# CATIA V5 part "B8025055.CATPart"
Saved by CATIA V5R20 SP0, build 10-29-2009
Part number: B8025055
Revision: 11
Definition: design
Nomenclature: B8025055
Source: made
Description: NOT SPECIFIED
Bounding box of the stored display mesh (mm): x -38 to 38, y -38 to 38, z -25 to 55
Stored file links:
  C:\Users\Utente\Desktop\3D files B802\B8025055.CATPart
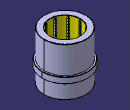
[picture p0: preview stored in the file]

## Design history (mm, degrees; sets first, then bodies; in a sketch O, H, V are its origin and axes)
Body1 "MANIFOLD_SOLID_BREP #38" (main body)
  Solid1: solid without history
Body2 "MANIFOLD_SOLID_BREP #76"
  Solid2: solid without history
Body3 "MANIFOLD_SOLID_BREP #114"
  Solid3: solid without history
Body4 "MANIFOLD_SOLID_BREP #152"
  Solid4: solid without history
Body5 "MANIFOLD_SOLID_BREP #190"
  Solid5: solid without history
Body6 "MANIFOLD_SOLID_BREP #228"
  Solid6: solid without history
Body7 "MANIFOLD_SOLID_BREP #266"
  Solid7: solid without history
Body8 "MANIFOLD_SOLID_BREP #304"
  Solid8: solid without history
Body9 "MANIFOLD_SOLID_BREP #2774"
  Solid9: solid without history
Body10 "MANIFOLD_SOLID_BREP #2812"
  Solid10: solid without history
Body11 "MANIFOLD_SOLID_BREP #2850"
  Solid11: solid without history
Body12 "MANIFOLD_SOLID_BREP #2888"
  Solid12: solid without history
Body13 "MANIFOLD_SOLID_BREP #2926"
  Solid13: solid without history
Body14 "MANIFOLD_SOLID_BREP #2964"
  Solid14: solid without history
Body15 "MANIFOLD_SOLID_BREP #3002"
  Solid15: solid without history
Body16 "MANIFOLD_SOLID_BREP #3040"
  Solid16: solid without history
Body17 "MANIFOLD_SOLID_BREP #3078"
  Solid17: solid without history
Body18 "MANIFOLD_SOLID_BREP #3116"
  Solid18: solid without history
Body19 "MANIFOLD_SOLID_BREP #3154"
  Solid19: solid without history
Body20 "MANIFOLD_SOLID_BREP #3192"
  Solid20: solid without history
Body21 "MANIFOLD_SOLID_BREP #3230"
  Solid21: solid without history
Body22 "MANIFOLD_SOLID_BREP #3268"
  Solid22: solid without history
Body23 "MANIFOLD_SOLID_BREP #3306"
  Solid23: solid without history
Body24 "MANIFOLD_SOLID_BREP #3344"
  Solid24: solid without history
Body25 "MANIFOLD_SOLID_BREP #3382"
  Solid25: solid without history
Body26 "MANIFOLD_SOLID_BREP #3420"
  Solid26: solid without history
Body27 "MANIFOLD_SOLID_BREP #3458"
  Solid27: solid without history
Body28 "MANIFOLD_SOLID_BREP #3496"
  Solid28: solid without history
Body29 "MANIFOLD_SOLID_BREP #3534"
  Solid29: solid without history
Body30 "MANIFOLD_SOLID_BREP #3572"
  Solid30: solid without history
Body31 "MANIFOLD_SOLID_BREP #3610"
  Solid31: solid without history
Body32 "MANIFOLD_SOLID_BREP #3648"
  Solid32: solid without history
Body33 "MANIFOLD_SOLID_BREP #3686"
  Solid33: solid without history
Body34 "MANIFOLD_SOLID_BREP #3724"
  Solid34: solid without history
Body35 "MANIFOLD_SOLID_BREP #3762"
  Solid35: solid without history
Body36 "MANIFOLD_SOLID_BREP #3800"
  Solid36: solid without history
Body37 "MANIFOLD_SOLID_BREP #3838"
  Solid37: solid without history
Body38 "MANIFOLD_SOLID_BREP #3876"
  Solid38: solid without history
Body39 "MANIFOLD_SOLID_BREP #3914"
  Solid39: solid without history
Body40 "MANIFOLD_SOLID_BREP #3952"
  Solid40: solid without history
Body41 "MANIFOLD_SOLID_BREP #3990"
  Solid41: solid without history
Body42 "MANIFOLD_SOLID_BREP #4028"
  Solid42: solid without history
Body43 "MANIFOLD_SOLID_BREP #4066"
  Solid43: solid without history
Body44 "MANIFOLD_SOLID_BREP #4104"
  Solid44: solid without history
Body45 "MANIFOLD_SOLID_BREP #4142"
  Solid45: solid without history
Body46 "MANIFOLD_SOLID_BREP #4180"
  Solid46: solid without history
Body47 "MANIFOLD_SOLID_BREP #4218"
  Solid47: solid without history
Body48 "MANIFOLD_SOLID_BREP #4256"
  Solid48: solid without history
Body49 "MANIFOLD_SOLID_BREP #4294"
  Solid49: solid without history
Body50 "MANIFOLD_SOLID_BREP #4332"
  Solid50: solid without history
Body51 "MANIFOLD_SOLID_BREP #4370"
  Solid51: solid without history
Body52 "MANIFOLD_SOLID_BREP #4408"
  Solid52: solid without history
Body53 "MANIFOLD_SOLID_BREP #4446"
  Solid53: solid without history
Body54 "MANIFOLD_SOLID_BREP #4484"
  Solid54: solid without history
Body55 "MANIFOLD_SOLID_BREP #4522"
  Solid55: solid without history
Body56 "MANIFOLD_SOLID_BREP #4560"
  Solid56: solid without history
Body57 "MANIFOLD_SOLID_BREP #4598"
  Solid57: solid without history
Body58 "MANIFOLD_SOLID_BREP #4636"
  Solid58: solid without history
Body59 "MANIFOLD_SOLID_BREP #4674"
  Solid59: solid without history
Body60 "MANIFOLD_SOLID_BREP #4712"
  Solid60: solid without history
Body61 "MANIFOLD_SOLID_BREP #4750"
  Solid61: solid without history
Body62 "MANIFOLD_SOLID_BREP #4788"
  Solid62: solid without history
Body63 "MANIFOLD_SOLID_BREP #4826"
  Solid63: solid without history
Body64 "MANIFOLD_SOLID_BREP #4864"
  Solid64: solid without history
Body65 "MANIFOLD_SOLID_BREP #4902"
  Solid65: solid without history
Body66 "MANIFOLD_SOLID_BREP #4940"
  Solid66: solid without history
Body67 "MANIFOLD_SOLID_BREP #4978"
  Solid67: solid without history
Body68 "MANIFOLD_SOLID_BREP #5016"
  Solid68: solid without history
Body69 "MANIFOLD_SOLID_BREP #5054"
  Solid69: solid without history
Body70 "MANIFOLD_SOLID_BREP #5092"
  Solid70: solid without history
Body71 "MANIFOLD_SOLID_BREP #5130"
  Solid71: solid without history
Body72 "MANIFOLD_SOLID_BREP #5168"
  Solid72: solid without history
Body73 "MANIFOLD_SOLID_BREP #5206"
  Solid73: solid without history
Body74 "MANIFOLD_SOLID_BREP #5244"
  Solid74: solid without history
Body75 "MANIFOLD_SOLID_BREP #5282"
  Solid75: solid without history
Body76 "MANIFOLD_SOLID_BREP #5320"
  Solid76: solid without history
Body77 "MANIFOLD_SOLID_BREP #5358"
  Solid77: solid without history
Body78 "MANIFOLD_SOLID_BREP #5396"
  Solid78: solid without history
Body79 "MANIFOLD_SOLID_BREP #5434"
  Solid79: solid without history
Body80 "MANIFOLD_SOLID_BREP #5472"
  Solid80: solid without history
Body81 "MANIFOLD_SOLID_BREP #5510"
  Solid81: solid without history
Body82 "MANIFOLD_SOLID_BREP #5548"
  Solid82: solid without history
Body83 "MANIFOLD_SOLID_BREP #5586"
  Solid83: solid without history
Body84 "MANIFOLD_SOLID_BREP #5624"
  Solid84: solid without history
Body85 "MANIFOLD_SOLID_BREP #5662"
  Solid85: solid without history
Body86 "MANIFOLD_SOLID_BREP #5700"
  Solid86: solid without history
Body87 "MANIFOLD_SOLID_BREP #5738"
  Solid87: solid without history
Body88 "MANIFOLD_SOLID_BREP #5776"
  Solid88: solid without history
Body89 "MANIFOLD_SOLID_BREP #5814"
  Solid89: solid without history
Body90 "MANIFOLD_SOLID_BREP #5852"
  Solid90: solid without history
Body91 "MANIFOLD_SOLID_BREP #5890"
  Solid91: solid without history
Body92 "MANIFOLD_SOLID_BREP #5928"
  Solid92: solid without history
Body93 "MANIFOLD_SOLID_BREP #5966"
  Solid93: solid without history
Body94 "MANIFOLD_SOLID_BREP #6004"
  Solid94: solid without history
Body95 "MANIFOLD_SOLID_BREP #6042"
  Solid95: solid without history
Body96 "MANIFOLD_SOLID_BREP #6080"
  Solid96: solid without history
Body97 "MANIFOLD_SOLID_BREP #6118"
  Solid97: solid without history
Body98 "MANIFOLD_SOLID_BREP #6156"
  Solid98: solid without history
Body99 "MANIFOLD_SOLID_BREP #6194"
  Solid99: solid without history
Body100 "MANIFOLD_SOLID_BREP #6232"
  Solid100: solid without history
Body101 "MANIFOLD_SOLID_BREP #6270"
  Solid101: solid without history
Body102 "MANIFOLD_SOLID_BREP #6308"
  Solid102: solid without history
Body103 "MANIFOLD_SOLID_BREP #6346"
  Solid103: solid without history
Body104 "MANIFOLD_SOLID_BREP #6384"
  Solid104: solid without history
Body105 "MANIFOLD_SOLID_BREP #6422"
  Solid105: solid without history
Body106 "MANIFOLD_SOLID_BREP #6460"
  Solid106: solid without history
Body107 "MANIFOLD_SOLID_BREP #6498"
  Solid107: solid without history
Body108 "MANIFOLD_SOLID_BREP #6536"
  Solid108: solid without history
Body109 "MANIFOLD_SOLID_BREP #6574"
  Solid109: solid without history
Body110 "MANIFOLD_SOLID_BREP #6612"
  Solid110: solid without history
Body111 "MANIFOLD_SOLID_BREP #6650"
  Solid111: solid without history
Body112 "MANIFOLD_SOLID_BREP #6688"
  Solid112: solid without history
Body113 "MANIFOLD_SOLID_BREP #6726"
  Solid113: solid without history
Body114 "MANIFOLD_SOLID_BREP #6764"
  Solid114: solid without history
Body115 "MANIFOLD_SOLID_BREP #6802"
  Solid115: solid without history
Body116 "MANIFOLD_SOLID_BREP #6840"
  Solid116: solid without history
Body117 "MANIFOLD_SOLID_BREP #6878"
  Solid117: solid without history
Body118 "MANIFOLD_SOLID_BREP #6916"
  Solid118: solid without history
Body119 "MANIFOLD_SOLID_BREP #6954"
  Solid119: solid without history
Body120 "MANIFOLD_SOLID_BREP #6992"
  Solid120: solid without history
Body121 "MANIFOLD_SOLID_BREP #7030"
  Solid121: solid without history
Body122 "MANIFOLD_SOLID_BREP #7068"
  Solid122: solid without history
Body123 "MANIFOLD_SOLID_BREP #7106"
  Solid123: solid without history
Body124 "MANIFOLD_SOLID_BREP #7144"
  Solid124: solid without history
Body125 "MANIFOLD_SOLID_BREP #7182"
  Solid125: solid without history
Body126 "MANIFOLD_SOLID_BREP #7220"
  Solid126: solid without history
Body127 "MANIFOLD_SOLID_BREP #7258"
  Solid127: solid without history
Body128 "MANIFOLD_SOLID_BREP #7296"
  Solid128: solid without history
Body129 "MANIFOLD_SOLID_BREP #7334"
  Solid129: solid without history
Body130 "MANIFOLD_SOLID_BREP #7372"
  Solid130: solid without history
Body131 "MANIFOLD_SOLID_BREP #7410"
  Solid131: solid without history
Body132 "MANIFOLD_SOLID_BREP #7448"
  Solid132: solid without history
Body133 "MANIFOLD_SOLID_BREP #7486"
  Solid133: solid without history
Body134 "MANIFOLD_SOLID_BREP #7524"
  Solid134: solid without history
Body135 "MANIFOLD_SOLID_BREP #7562"
  Solid135: solid without history
Body136 "MANIFOLD_SOLID_BREP #7600"
  Solid136: solid without history
Body137 "MANIFOLD_SOLID_BREP #7638"
  Solid137: solid without history
Body138 "MANIFOLD_SOLID_BREP #7676"
  Solid138: solid without history
Body139 "MANIFOLD_SOLID_BREP #7714"
  Solid139: solid without history
Body140 "MANIFOLD_SOLID_BREP #7752"
  Solid140: solid without history
Body141 "MANIFOLD_SOLID_BREP #7790"
  Solid141: solid without history
Body142 "MANIFOLD_SOLID_BREP #7828"
  Solid142: solid without history
Body143 "MANIFOLD_SOLID_BREP #7866"
  Solid143: solid without history
Body144 "MANIFOLD_SOLID_BREP #7904"
  Solid144: solid without history
Body145 "MANIFOLD_SOLID_BREP #7942"
  Solid145: solid without history
Body146 "MANIFOLD_SOLID_BREP #7980"
  Solid146: solid without history
Body147 "MANIFOLD_SOLID_BREP #8018"
  Solid147: solid without history
Body148 "MANIFOLD_SOLID_BREP #8056"
  Solid148: solid without history
Body149 "MANIFOLD_SOLID_BREP #8094"
  Solid149: solid without history
Body150 "MANIFOLD_SOLID_BREP #8132"
  Solid150: solid without history
Body151 "MANIFOLD_SOLID_BREP #8170"
  Solid151: solid without history
Body152 "MANIFOLD_SOLID_BREP #8208"
  Solid152: solid without history
Body153 "MANIFOLD_SOLID_BREP #8246"
  Solid153: solid without history
Body154 "MANIFOLD_SOLID_BREP #8284"
  Solid154: solid without history
Body155 "MANIFOLD_SOLID_BREP #8322"
  Solid155: solid without history
Body156 "MANIFOLD_SOLID_BREP #8360"
  Solid156: solid without history
Body157 "MANIFOLD_SOLID_BREP #8398"
  Solid157: solid without history
Body158 "MANIFOLD_SOLID_BREP #8436"
  Solid158: solid without history
Body159 "MANIFOLD_SOLID_BREP #8474"
  Solid159: solid without history
Body160 "MANIFOLD_SOLID_BREP #8512"
  Solid160: solid without history
Body161 "MANIFOLD_SOLID_BREP #8550"
  Solid161: solid without history
Body162 "MANIFOLD_SOLID_BREP #8588"
  Solid162: solid without history
Body163 "MANIFOLD_SOLID_BREP #8626"
  Solid163: solid without history
Body164 "MANIFOLD_SOLID_BREP #8664"
  Solid164: solid without history
Body165 "MANIFOLD_SOLID_BREP #8702"
  Solid165: solid without history
Body166 "MANIFOLD_SOLID_BREP #8740"
  Solid166: solid without history
Body167 "MANIFOLD_SOLID_BREP #8778"
  Solid167: solid without history
Body168 "MANIFOLD_SOLID_BREP #8816"
  Solid168: solid without history
Body169 "MANIFOLD_SOLID_BREP #8854"
  Solid169: solid without history
Body170 "MANIFOLD_SOLID_BREP #8892"
  Solid170: solid without history
Body171 "MANIFOLD_SOLID_BREP #8930"
  Solid171: solid without history
Body172 "MANIFOLD_SOLID_BREP #8968"
  Solid172: solid without history
Body173 "MANIFOLD_SOLID_BREP #9006"
  Solid173: solid without history
Body174 "MANIFOLD_SOLID_BREP #9044"
  Solid174: solid without history
Body175 "MANIFOLD_SOLID_BREP #9082"
  Solid175: solid without history
Body176 "MANIFOLD_SOLID_BREP #9120"
  Solid176: solid without history
Body177 "MANIFOLD_SOLID_BREP #9158"
  Solid177: solid without history
Body178 "MANIFOLD_SOLID_BREP #9196"
  Solid178: solid without history
Body179 "MANIFOLD_SOLID_BREP #9234"
  Solid179: solid without history
Body180 "MANIFOLD_SOLID_BREP #9272"
  Solid180: solid without history
Body181 "MANIFOLD_SOLID_BREP #9310"
  Solid181: solid without history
